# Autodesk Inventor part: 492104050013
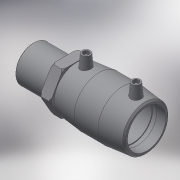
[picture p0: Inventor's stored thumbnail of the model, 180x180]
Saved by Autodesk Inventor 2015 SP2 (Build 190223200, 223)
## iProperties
Created: 2017-06
Part Number: 492104050013
Material: Generic
Description: PLASSON Male Transition Coupler 50 x 1.1/4"
Document SubType Name: Modeling
Designer: KIM
Mass: 212.267 g
Surface Area: 546.042 cm^2
Volume: 212.267 cm^3
Density: 1 g/cm^3
Appearance: Default
Author: KIM
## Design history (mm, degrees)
derived "492104.ipt"
feature "Solid1::492104.ipt"
tag "TaggingFeature1"
body "Solid1"
other parameters: "d0" = 101, "d2" = 67, "d3" = 49, "d4" = 33.66667, "d5" = 60.3, "d6" = 47.5, "d8" = 168 deg, "d10" = 19.6, "d11" = 6.53333, "d29" = 51, "d30" = 14, "d31" = 35.35, "d34" = 5 deg, "d41" = 4, "d42" = 14, "d43" = 0, "d48" = 3, "d49" = 0, "d57" = 38, "d58" = 41.91, "d59" = 33.528, "d60" = 32.4, "d61" = 67, "d62" = 0.8382, "d65" = 2.01, "d70" = 0.1, "d71" = 36, "d72" = 9, "d73" = 19.6, "d75" = 0, "L_" = 137, "L_1" = 49, "D_1" = 67, "A_" = 51, "d_2" = 12, "L_2" = 36, "D_" = 38, "R_" = 41.91
